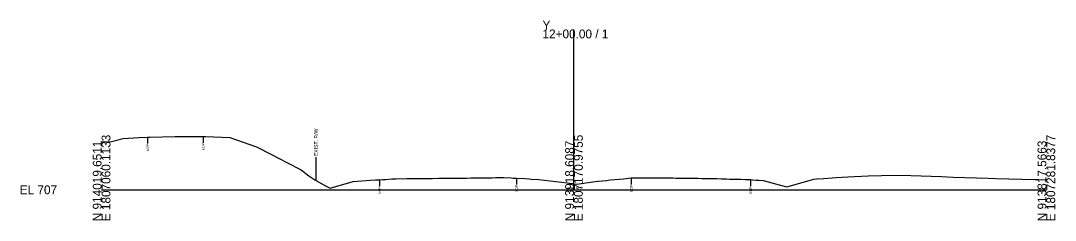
# Model space of a CAD drawing. Extents: x -26 to 3303, y -30 to 9580.
# Drawn here: x -25.7 to 302.8, y 1990.3 to 2053.7 of the extents above; entities that cross this region are included whole.
import ezdxf

# ---------------------------------------------------------------- set-up
doc = ezdxf.new("R2010")
doc.units = 0
for name, color, linetype in [('Exist Cross Section Cell', 7, 'Continuous'), ('Exist XS Center Line Elevation Label', 7, 'Continuous'), ('Exist XS Ground Line', 7, 'Continuous'), ('Old_Level_10', 7, 'Continuous')]:
    doc.layers.add(name, color=color, linetype=linetype)

msp = doc.modelspace()

# ---------------------------------------------------------------- linework, layer by layer
at = {"layer": 'Exist Cross Section Cell'}
for p, q in [((150, 2000), (150, 2050.89)), ((0, 2000), (150, 2000)), ((150, 2000), (300, 2000))]:
    msp.add_line(p, q, dxfattribs=at)
at = {"layer": 'Exist XS Ground Line'}
msp.add_lwpolyline([(0, 2015.29), (1.94, 2015.18), (2.34, 2015.2), (3.1, 2015.36), (6.86, 2016.26), (11.85, 2016.55), (14.54, 2016.71), (15.24, 2016.73), (23.33, 2016.96), (24.11, 2016.96), (32.24, 2016.96), (33.12, 2016.96), (40.67, 2016.65), (42.83, 2015.85), (49.22, 2013.64), (53.97, 2011.23), (58.86, 2008.69), (63.38, 2006.36), (65.82, 2004.45), (67.71, 2003.16), (71.11, 2001.27), (72.53, 2000.56), (74.43, 2001.08), (79.93, 2002.66), (85.38, 2003.03), (87, 2003.13), (88.22, 2003.21), (89.35, 2003.26), (90.17, 2003.3), (92.13, 2003.47), (93.16, 2003.49), (93.57, 2003.5), (96.95, 2003.54), (98.6, 2003.57), (100.41, 2003.58), (103.94, 2003.6), (104.37, 2003.6), (104.92, 2003.61), (107.1, 2003.64), (107.45, 2003.64), (107.83, 2003.65), (109.2, 2003.67), (110.47, 2003.68), (111.55, 2003.69), (112.75, 2003.7), (113.85, 2003.71), (114.95, 2003.73), (115.83, 2003.74), (117.24, 2003.76), (118.05, 2003.77), (118.94, 2003.79), (120.61, 2003.81), (122.66, 2003.83), (123.36, 2003.83), (124.01, 2003.84), (125.13, 2003.85), (126.4, 2003.86), (127.57, 2003.89), (130.1, 2003.75), (130.65, 2003.73), (131.78, 2003.71), (134.4, 2003.54), (135.79, 2003.46), (136.52, 2003.41), (138.87, 2003.26), (149.6, 2001.95), (150, 2001.9), (150.91, 2001.79), (156.71, 2002.59), (157.82, 2002.75), (160.31, 2002.98), (160.83, 2003.04), (161.62, 2003.11), (162.95, 2003.24), (165.72, 2003.51), (168.2, 2003.75), (168.74, 2003.75), (170.89, 2003.75), (171.61, 2003.79), (172.28, 2003.84), (174.3, 2003.82), (174.75, 2003.81), (175.88, 2003.81), (178.35, 2003.78), (181.5, 2003.75), (182.29, 2003.74), (184.1, 2003.71), (184.89, 2003.69), (185.74, 2003.68), (187.05, 2003.66), (188.25, 2003.65), (188.81, 2003.65), (189.44, 2003.64), (190.59, 2003.63), (191.62, 2003.62), (192.36, 2003.6), (193.19, 2003.59), (194.85, 2003.57), (195.34, 2003.56), (196.84, 2003.49), (198.4, 2003.43), (199.43, 2003.41), (200.55, 2003.38), (201.81, 2003.35), (202.98, 2003.32), (204.31, 2003.29), (205.2, 2003.27), (206.1, 2003.24), (206.81, 2003.19), (207.83, 2003.1), (208.37, 2003.06), (208.73, 2003.05), (210.05, 2002.93), (216.69, 2001.19), (217.64, 2000.96), (225.38, 2003.17), (226.17, 2003.4), (227.09, 2003.45), (229.32, 2003.62), (233.27, 2003.91), (237.01, 2004.14), (243.39, 2004.45), (251.85, 2004.59), (256.92, 2004.51), (266.7, 2004.18), (270.45, 2004.05), (281.54, 2003.67), (283.98, 2003.59), (296.39, 2003.24), (297.51, 2003.22), (300, 2003.19)], dxfattribs=at)
at = {"layer": 'Old_Level_10'}
for p, q in [((14.54, 2016.71), (14.54, 2014.66)), ((32.24, 2016.96), (32.24, 2014.91)), ((68.07, 2010.36), (68.07, 2002.96)), ((88.22, 2003.21), (88.22, 2001.16)), ((131.78, 2003.71), (131.78, 2001.66)), ((168.2, 2003.75), (168.2, 2001.7)), ((206.1, 2003.24), (206.1, 2001.19))]:
    msp.add_line(p, q, dxfattribs=at)

# ---------------------------------------------------------------- texts
at = {"layer": 'Exist Cross Section Cell'}
for s, p in [('Y', (140, 2050.89)), ('12+00.00 / 1', (140, 2048.09)), ('EL 707', (-26, 1998.6))]:
    msp.add_text(s, height=2.8, dxfattribs=at).set_placement(p)
for s, p in [('E 1807060.1133', (2.8, 1990)), ('E 1807170.9755', (152.8, 1990)), ('E 1807281.8377', (302.8, 1990)), ('N 914019.6511', (0, 1990)), ('N 913918.6087', (150, 1990)), ('N 913817.5663', (300, 1990))]:
    msp.add_text(s, height=2.8, rotation=90, dxfattribs=at).set_placement(p)
at = {"layer": 'Exist XS Center Line Elevation Label'}
msp.add_text('708.90', height=1, dxfattribs=at).set_placement((147.85, 1999.9))
at = {"layer": 'Old_Level_10'}
for s, height, p in [('EXIST. R/W', 1.181, (68.66, 2010.66)), ('EOP', 0.787, (14.94, 2012.26)), ('EOP', 0.787, (32.63, 2012.52)), ('EOP', 0.787, (88.62, 1998.77)), ('EOP', 0.787, (132.18, 1999.26)), ('EOP', 0.787, (168.6, 1999.3)), ('EOP', 0.787, (206.49, 1998.8))]:
    msp.add_text(s, height=height, rotation=90, dxfattribs=at).set_placement(p)

doc.saveas('drawing.dxf')
